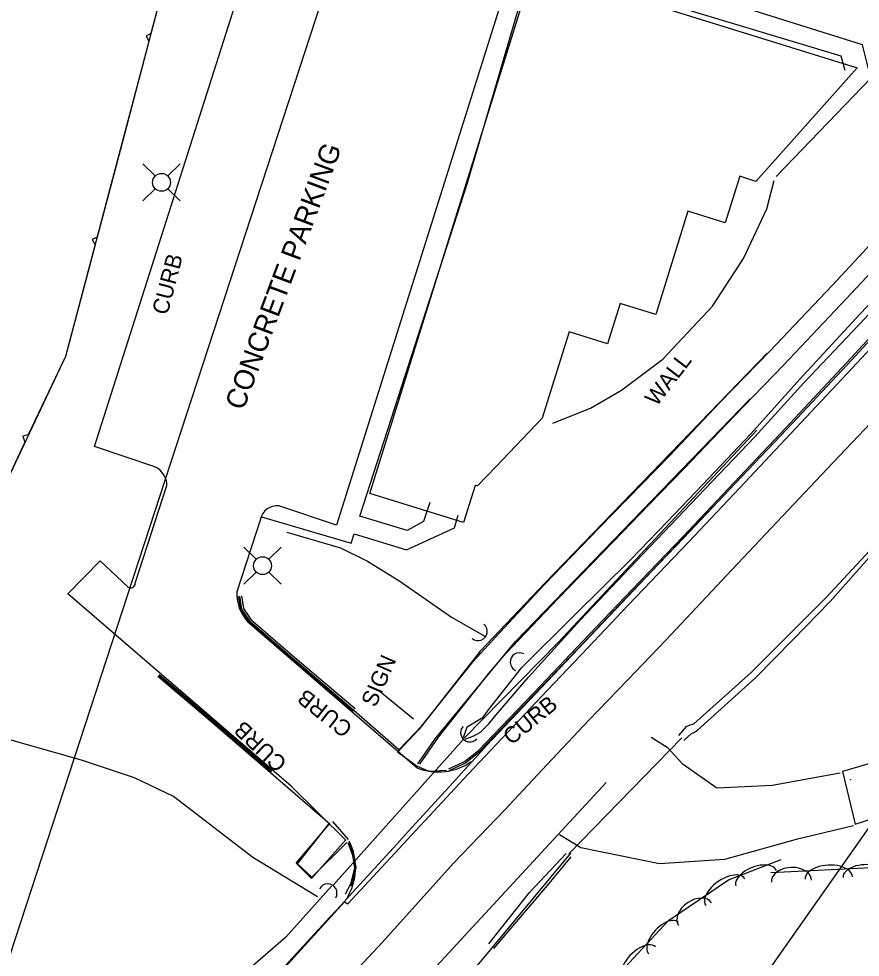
# Model space of a CAD drawing. Extents: x 978516 to 993312, y 1836504 to 1846212.
# Drawn here: x 982203.8 to 982411.6, y 1842943.3 to 1843174.9 of the extents above; entities that cross this region are included whole.
import ezdxf

# ---------------------------------------------------------------- set-up
doc = ezdxf.new("R2010")
doc.units = 0
for name, color, linetype in [('S_BUILDING', 7, 'Continuous'), ('S_CROSS_DRAIN', 7, 'Continuous'), ('S_CURB', 7, 'Continuous'), ('S_CURB_ANNOT', 7, 'Continuous'), ('S_DITCHLINE', 7, 'Continuous'), ('S_DRIVEWAY', 7, 'Continuous'), ('S_EDGE_CONCRETE', 7, 'Continuous'), ('S_EDGE_PAVEMENT', 7, 'Continuous'), ('S_IRON_PIN_ANNOT', 7, 'Continuous'), ('S_MSC_PT_SYM', 7, 'Continuous'), ('S_PARKING', 7, 'Continuous'), ('S_PARKING_ANNOT', 7, 'Continuous'), ('S_PAVEMENT_CROWN', 7, 'Continuous'), ('S_SIDE_DRAIN', 7, 'Continuous'), ('S_SIDEWALK', 7, 'Continuous'), ('S_SIGN', 7, 'Continuous'), ('S_SIGN_ANNOT', 7, 'Continuous'), ('S_STREAM', 7, 'Continuous'), ('S_TREE', 7, 'Continuous'), ('S_UTILITY_POLE', 7, 'Continuous'), ('S_WALL_ANNOT', 7, 'Continuous')]:
    doc.layers.add(name, color=color, linetype=linetype)

msp = doc.modelspace()

# ---------------------------------------------------------------- linework, layer by layer
at = {"layer": 'S_BUILDING'}
msp.add_lwpolyline([(982290.5, 1843057.74), (982330.9, 1843187.63), (982410.76, 1843162.8), (982385.82, 1843134.75), (982381.83, 1843136.09), (982378.24, 1843124.54), (982369.01, 1843127.41), (982361.09, 1843101.95), (982352.31, 1843104.68), (982349.2, 1843094.68), (982339.69, 1843097.63), (982333.07, 1843076.34), (982321.59, 1843064.31), (982317.04, 1843059.59), (982316.52, 1843059.75), (982313.65, 1843050.54)], close=True, dxfattribs=at)
at = {"layer": 'S_CROSS_DRAIN'}
for centre, start, end in [((982317.18, 1843023.71), 231.2419, 51.5711), ((982327.45, 1843016.11), 63.0314, 243.3606), ((982315.2, 1842998.71), 137.6159, 317.9451), ((982280.09, 1842959.05), 330.1073, 150.4365)]:
    msp.add_arc(centre, 2.3, start, end, dxfattribs=at)
at = {"layer": 'S_CURB'}
for points in [[(982310.01, 1842989.75), (982313.88, 1842991.61), (982317.2, 1842994.25), (982332.7, 1843010.35), (982343.01, 1843021.21), (982353.32, 1843032.07), (982367.67, 1843046.99), (982380.41, 1843060.45), (982393.16, 1843073.92), (982409.26, 1843091.11), (982418.22, 1843100.89), (982427.18, 1843110.67), (982434.94, 1843124.55)], [(982310.01, 1842989.75), (982313.88, 1842991.61), (982317.2, 1842994.25), (982332.7, 1843010.35), (982343.01, 1843021.21), (982353.32, 1843032.07), (982367.67, 1843046.99), (982380.41, 1843060.45), (982393.16, 1843073.92), (982409.26, 1843091.11), (982418.22, 1843100.89), (982427.18, 1843110.67), (982434.94, 1843124.55)], [(982310.19, 1842989.39), (982314.09, 1842991.27), (982317.47, 1842993.96), (982332.99, 1843010.07), (982343.3, 1843020.93), (982353.61, 1843031.79), (982367.95, 1843046.71), (982380.7, 1843060.18), (982393.45, 1843073.64), (982409.55, 1843090.84), (982418.53, 1843100.64), (982427.5, 1843110.44), (982435.29, 1843124.36)], [(982310.19, 1842989.39), (982314.09, 1842991.27), (982317.47, 1842993.96), (982332.99, 1843010.07), (982343.3, 1843020.93), (982353.61, 1843031.79), (982367.95, 1843046.71), (982380.7, 1843060.18), (982393.45, 1843073.64), (982409.55, 1843090.84), (982418.53, 1843100.64), (982427.5, 1843110.44), (982435.29, 1843124.36)], [(982258, 1843032.32), (982258.55, 1843029.05), (982260.55, 1843026.07), (982272, 1843016.16), (982286.37, 1843004.04)], [(982258.3, 1843032.37), (982258.83, 1843029.16), (982260.78, 1843026.27), (982272.19, 1843016.39), (982286.57, 1843004.26), (982297.68, 1842994.54)], [(982238.2, 1843012.67), (982250.58, 1843002.14), (982266, 1842988.86), (982280.62, 1842976.23)], [(982238.39, 1843012.9), (982250.78, 1843002.37), (982266.2, 1842989.08)], [(982238.39, 1843012.9), (982250.78, 1843002.37), (982266.2, 1842989.08)], [(982285.07, 1842971.56), (982286.25, 1842968.42), (982286.74, 1842965.35), (982285.69, 1842961.28), (982284.44, 1842958.81)], [(982285.42, 1842971.49), (982286.54, 1842968.5), (982287.04, 1842965.33), (982285.98, 1842961.18), (982285.78, 1842960.79)]]:
    msp.add_lwpolyline(points, dxfattribs=at)
at = {"layer": 'S_DITCHLINE'}
for points in [[(982313.59, 1842997.52), (982314.52, 1843000.14), (982318.5, 1843002.54), (982319.75, 1843004.37), (982328.05, 1843014.77), (982341.11, 1843027.79), (982354.9, 1843041.43), (982363.81, 1843050.68), (982372.72, 1843059.93), (982384.54, 1843072.5), (982396.63, 1843085.98), (982411.57, 1843102.1), (982419.68, 1843110.65), (982424, 1843116.04), (982429.13, 1843125.27), (982430.93, 1843128.27), (982432.31, 1843130.79), (982432.8, 1843131.44), (982434.64, 1843132.19), (982437.24, 1843133.95)], [(982313.59, 1842997.52), (982314.52, 1843000.14), (982318.5, 1843002.54), (982319.75, 1843004.37), (982328.05, 1843014.77), (982341.11, 1843027.79), (982354.9, 1843041.43), (982363.81, 1843050.68), (982372.72, 1843059.93), (982384.54, 1843072.5), (982396.63, 1843085.98), (982411.57, 1843102.1), (982419.68, 1843110.65), (982424, 1843116.04), (982429.13, 1843125.27), (982430.93, 1843128.27), (982432.31, 1843130.79), (982432.8, 1843131.44), (982434.64, 1843132.19), (982437.24, 1843133.95)], [(982314.07, 1842997.1), (982316.2, 1842997.94), (982317.81, 1842998.81), (982319.86, 1843000.89), (982321.69, 1843003.14), (982329.58, 1843012.28), (982342.49, 1843026.52), (982356.26, 1843041), (982373.23, 1843058.77), (982385.5, 1843071.71), (982397.63, 1843085.05), (982412.79, 1843101.02), (982420.69, 1843109.93), (982424.98, 1843115.3), (982430.76, 1843124.87), (982431.76, 1843127.66), (982432.61, 1843128.21)], [(982314.07, 1842997.1), (982316.2, 1842997.94), (982317.81, 1842998.81), (982319.86, 1843000.89), (982321.69, 1843003.14), (982329.58, 1843012.28), (982342.49, 1843026.52), (982356.26, 1843041), (982373.23, 1843058.77), (982385.5, 1843071.71), (982397.63, 1843085.05), (982412.79, 1843101.02), (982420.69, 1843109.93), (982424.98, 1843115.3), (982430.76, 1843124.87), (982431.76, 1843127.66), (982432.61, 1843128.21)], [(982366.78, 1842998.03), (982368.67, 1843000.22), (982369.54, 1843000.64), (982370.5, 1843000.9), (982384.64, 1843013.54), (982393.93, 1843022.83), (982403.23, 1843032.13), (982419.18, 1843049.38)], [(982366.78, 1842998.03), (982368.67, 1843000.22), (982369.54, 1843000.64), (982370.5, 1843000.9), (982384.64, 1843013.54), (982393.93, 1843022.83), (982403.23, 1843032.13), (982419.18, 1843049.38)], [(982367.98, 1842996.74), (982369.91, 1842998.51), (982370.31, 1842998.64), (982371.31, 1842999.2), (982385.67, 1843012.22), (982394.91, 1843021.65), (982404.14, 1843031.08), (982420.18, 1843049.22)], [(982319.89, 1842946.58), (982329.95, 1842959.26), (982338.95, 1842968.86)], [(982340.1, 1842968.01), (982334.26, 1842960.95), (982321, 1842945.38)]]:
    msp.add_lwpolyline(points, dxfattribs=at)
at = {"layer": 'S_DRIVEWAY'}
for points in [[(982258.79, 1843032.45), (982259.31, 1843029.35), (982261.16, 1843026.61), (982272.52, 1843016.77), (982286.89, 1843004.64)], [(982238.52, 1843013.05), (982250.91, 1843002.52), (982266.33, 1842989.24)], [(982238.52, 1843013.05), (982250.91, 1843002.52), (982266.33, 1842989.24)], [(982359.97, 1842997.61), (982363.91, 1842995.15), (982367.56, 1842991.1), (982376.15, 1842985.11), (982389.79, 1842985.76), (982406.62, 1842988.77)], [(982359.97, 1842997.61), (982363.91, 1842995.15), (982367.56, 1842991.1), (982376.15, 1842985.11), (982389.79, 1842985.76), (982406.62, 1842988.77)], [(982297.36, 1842993.94), (982302.17, 1842990.4), (982305.02, 1842989.2), (982309.43, 1842989.41)], [(982281.32, 1842976.8), (982285.15, 1842972.33)], [(982409.93, 1842975.74), (982395.76, 1842972.31), (982378.01, 1842967.38), (982361.97, 1842966.36), (982342.56, 1842970.27), (982337.35, 1842973.46)], [(982409.93, 1842975.74), (982395.76, 1842972.31), (982378.01, 1842967.38), (982361.97, 1842966.36), (982342.56, 1842970.27), (982337.35, 1842973.46)]]:
    msp.add_lwpolyline(points, dxfattribs=at)
at = {"layer": 'S_EDGE_CONCRETE'}
for points in [[(982410.28, 1842976.09), (982425.13, 1842980.92), (982422.37, 1842993.58), (982407.2, 1842989.13)], [(982407.2, 1842989.13), (982410.28, 1842976.09)]]:
    msp.add_lwpolyline(points, dxfattribs=at)
at = {"layer": 'S_EDGE_PAVEMENT'}
for points in [[(982262.81, 1842933.38), (982273.52, 1842945.14), (982284.22, 1842956.91), (982285.09, 1842956.45), (982301.82, 1842974.54), (982314.78, 1842988.42), (982324.57, 1842998.8), (982334.36, 1843009.18), (982344.31, 1843019.68), (982354.26, 1843030.18), (982369.14, 1843045.7), (982381.73, 1843059.08), (982394.31, 1843072.45), (982410.8, 1843089.97), (982425.98, 1843106.39), (982439.97, 1843122.26), (982437.62, 1843124.47), (982439.48, 1843126.59), (982448.32, 1843135.88), (982456.89, 1843144.96), (982470.98, 1843160.83), (982473.17, 1843164.88), (982487.85, 1843181.85)], [(982262.81, 1842933.38), (982273.52, 1842945.14), (982284.22, 1842956.91), (982285.09, 1842956.45), (982301.82, 1842974.54), (982314.78, 1842988.42), (982324.57, 1842998.8), (982334.36, 1843009.18), (982344.31, 1843019.68), (982354.26, 1843030.18), (982369.14, 1843045.7), (982381.73, 1843059.08), (982394.31, 1843072.45), (982410.8, 1843089.97), (982425.98, 1843106.39), (982439.97, 1843122.26), (982437.62, 1843124.47), (982439.48, 1843126.59), (982448.32, 1843135.88), (982456.89, 1843144.96), (982470.98, 1843160.83), (982473.17, 1843164.88), (982487.85, 1843181.85)], [(982319.32, 1842995.54), (982375.31, 1843054.59)], [(982348.83, 1842986.38), (982259.18, 1842889.28), (982226.37, 1842852.75)]]:
    msp.add_lwpolyline(points, dxfattribs=at)
msp.add_ellipse((982031.71, 1843314.23), major_axis=(1334.75, 1486.11), ratio=0.213781, start_param=4.624147, end_param=4.689901, dxfattribs=at)
at = {"layer": 'S_IRON_PIN_ANNOT'}
msp.add_lwpolyline([(982335.67, 1843075.11), (982344.96, 1843078.82), (982352.58, 1843083.22), (982362.84, 1843090.89), (982375.05, 1843103.96), (982382.71, 1843115.72), (982388.47, 1843128.01), (982390.29, 1843135)], dxfattribs=at)
at = {"layer": 'S_MSC_PT_SYM'}
msp.add_lwpolyline([(982409.17, 1842987.12), (982409.17, 1842987.17), (982409.17, 1842987.12), (982409.12, 1842987.12), (982409.17, 1842987.12), (982409.17, 1842987.07), (982409.17, 1842987.12), (982409.22, 1842987.12)], dxfattribs=at)
at = {"layer": 'S_PARKING'}
for points in [[(982237.45, 1843064.3), (982222.53, 1843069.32), (982263.23, 1843197.33), (982279.77, 1843192.12)], [(982237.45, 1843064.3), (982222.53, 1843069.32), (982263.23, 1843197.33), (982279.77, 1843192.12)], [(982237.45, 1843064.3), (982222.53, 1843069.32), (982263.23, 1843197.33), (982279.77, 1843192.12)], [(982305.84, 1843183.12), (982322.39, 1843177.48), (982282.24, 1843049.96), (982268.03, 1843054.67)], [(982305.84, 1843183.12), (982322.39, 1843177.48), (982282.24, 1843049.96), (982268.03, 1843054.67)], [(982305.84, 1843183.12), (982322.39, 1843177.48), (982282.24, 1843049.96), (982268.03, 1843054.67)], [(982232.56, 1843035.63), (982240.42, 1843059.74)], [(982232.56, 1843035.63), (982240.42, 1843059.74)], [(982232.56, 1843035.63), (982240.42, 1843059.74)], [(982263.47, 1843051.39), (982257.63, 1843033.46)], [(982263.47, 1843051.39), (982257.63, 1843033.46)], [(982263.47, 1843051.39), (982257.63, 1843033.46)], [(982284.68, 1842972.07), (982271.1, 1842985.51), (982215.92, 1843032.98), (982223.89, 1843041.15), (982230.74, 1843034.68)], [(982284.68, 1842972.07), (982271.1, 1842985.51), (982215.92, 1843032.98), (982223.89, 1843041.15), (982230.74, 1843034.68)], [(982284.68, 1842972.07), (982271.1, 1842985.51), (982215.92, 1843032.98), (982223.89, 1843041.15), (982230.74, 1843034.68)], [(982260.26, 1843026.14), (982302.18, 1842989.98)], [(982260.26, 1843026.14), (982302.18, 1842989.98)], [(982260.26, 1843026.14), (982302.18, 1842989.98)]]:
    msp.add_lwpolyline(points, dxfattribs=at)
for centre, major_axis, ratio, start_param, end_param in [((982237.16, 1843060.88), (-2.2, 3.3), 0.729044, 3.943969, 5.454657), ((982237.16, 1843060.88), (-2.2, 3.3), 0.729044, 3.943969, 5.454657), ((982237.16, 1843060.88), (-2.2, 3.3), 0.729044, 3.943969, 5.454657), ((982267.51, 1843050.53), (0.48, 4.14), 0.989001, 6.273379, 7.760035), ((982267.51, 1843050.53), (0.48, 4.14), 0.989001, 6.273379, 7.760035), ((982267.51, 1843050.53), (0.48, 4.14), 0.989001, 6.273379, 7.760035), ((982231.41, 1843035.56), (1.06, -0.48), 0.95124, 4.498397, 6.784956), ((982231.41, 1843035.56), (1.06, -0.48), 0.95124, 4.498397, 6.784956), ((982231.41, 1843035.56), (1.06, -0.48), 0.95124, 4.498397, 6.784956), ((982268.46, 1843033.26), (0, -10.9), 0.993118, 4.694677, 5.424665), ((982268.46, 1843033.26), (0, -10.9), 0.993118, 4.694677, 5.424665), ((982268.46, 1843033.26), (0, -10.9), 0.993118, 4.694677, 5.424665), ((982307.52, 1843000.62), (12.96, 0.65), 0.894333, 4.243565, 5.329373), ((982307.52, 1843000.62), (12.96, 0.65), 0.894333, 4.243565, 5.329373), ((982307.52, 1843000.62), (12.96, 0.65), 0.894333, 4.243565, 5.329373), ((982272.39, 1842965.26), (11.61, 8.88), 0.992741, 5.081123, 6.100349)]:
    msp.add_ellipse(centre, major_axis=major_axis, ratio=ratio, start_param=start_param, end_param=end_param, dxfattribs=at)
at = {"layer": 'S_PAVEMENT_CROWN'}
msp.add_lwpolyline([(982282.98, 1842935.62), (982293.66, 1842947), (982302.39, 1842956.74), (982311.12, 1842966.49), (982323.85, 1842979.66), (982334.21, 1842990.74), (982344.56, 1843001.82), (982354.08, 1843011.66), (982363.59, 1843021.51), (982378.65, 1843037.56), (982390.97, 1843050.64), (982403.29, 1843063.73), (982420.37, 1843081.7), (982434.99, 1843097.55), (982448.57, 1843111.64), (982459.98, 1843124.19), (982470.63, 1843135.54), (982484.52, 1843150.65), (982494.5, 1843162.1), (982504.48, 1843173.55), (982517.52, 1843188.84)], dxfattribs=at)
at = {"layer": 'S_SIDE_DRAIN'}
for p, q in [((982281.53, 1842961.15), (982313.68, 1842997.2)), ((982339.6, 1842968.75), (982367.51, 1842997.41))]:
    msp.add_line(p, q, dxfattribs=at)
at = {"layer": 'S_SIDEWALK'}
for points in [[(982390.8, 1843135.97), (982414.13, 1843160.29), (982412.14, 1843168.51), (982333.42, 1843193.22), (982326.15, 1843189.45), (982322.34, 1843177.58)], [(982305.3, 1843055.48), (982303.76, 1843050.81), (982299.68, 1843048.58), (982288.06, 1843052.16), (982314.57, 1843134.46), (982329.35, 1843184.77), (982333.71, 1843187.81), (982406.79, 1843165.77), (982407.78, 1843162.25)], [(982297.79, 1842994.59), (982303.36, 1843000.42), (982316.12, 1843016.33), (982320.57, 1843021.22), (982333.52, 1843035.16), (982347.16, 1843049.35), (982364.57, 1843067.13), (982376.95, 1843080.27), (982389.24, 1843092.86), (982404.62, 1843109.11), (982412.24, 1843117.28), (982417.07, 1843122.54), (982433.13, 1843139.54), (982445.17, 1843151.93), (982457.08, 1843164.66), (982464.33, 1843172.15), (982469.15, 1843178.53)], [(982297.79, 1842994.59), (982303.36, 1843000.42), (982316.12, 1843016.33), (982320.57, 1843021.22), (982333.52, 1843035.16), (982347.16, 1843049.35), (982364.57, 1843067.13), (982376.95, 1843080.27), (982389.24, 1843092.86), (982404.62, 1843109.11), (982412.24, 1843117.28), (982417.07, 1843122.54), (982433.13, 1843139.54), (982445.17, 1843151.93), (982457.08, 1843164.66), (982464.33, 1843172.15), (982469.15, 1843178.53)], [(982302.84, 1842990.91), (982307.45, 1842997.59), (982319.82, 1843013.22), (982324.05, 1843018.23), (982337.01, 1843031.78), (982350.66, 1843045.92), (982359.35, 1843054.9), (982368.05, 1843063.89), (982380.33, 1843076.77), (982392.72, 1843089.54), (982408.07, 1843105.75), (982415.77, 1843113.91), (982420.39, 1843118.84), (982436.22, 1843135.72), (982448.71, 1843149.05), (982460.53, 1843161.31), (982467.87, 1843168.8), (982471.61, 1843172.36)], [(982302.84, 1842990.91), (982307.45, 1842997.59), (982319.82, 1843013.22), (982324.05, 1843018.23), (982337.01, 1843031.78), (982350.66, 1843045.92), (982359.35, 1843054.9), (982368.05, 1843063.89), (982380.33, 1843076.77), (982392.72, 1843089.54), (982408.07, 1843105.75), (982415.77, 1843113.91), (982420.39, 1843118.84), (982436.22, 1843135.72), (982448.71, 1843149.05), (982460.53, 1843161.31), (982467.87, 1843168.8), (982471.61, 1843172.36)], [(982388.58, 1843092.34), (982333.79, 1843035.68), (982317.71, 1843018.84), (982302.66, 1842999.6), (982297.57, 1842994.15)], [(982302.31, 1842990.99), (982306.59, 1842997.2), (982326.49, 1843021.19), (982384.36, 1843081.09)], [(982263.79, 1843051.98), (982285.92, 1843045.48), (982286.62, 1843047.8), (982299.56, 1843043.83), (982311.43, 1843049.27), (982312.29, 1843052.42)], [(982284.55, 1842972.27), (982276.07, 1842962.74), (982272.28, 1842966.46), (982280.59, 1842976.28)], [(982284.81, 1842971.57), (982276.14, 1842963.03), (982272.66, 1842966.28), (982280.52, 1842976.34)]]:
    msp.add_lwpolyline(points, dxfattribs=at)
at = {"layer": 'S_SIGN'}
msp.add_lwpolyline([(982301.29, 1843002.03), (982292.58, 1843009.2)], dxfattribs=at)
at = {"layer": 'S_STREAM'}
for points in [[(982313.77, 1842997.32), (982337, 1843020.93), (982386.02, 1843073.41)], [(982270.02, 1843048.23), (982283.29, 1843044.29), (982289.91, 1843041.02), (982297.93, 1843036.06), (982310.63, 1843027.24), (982318.91, 1843022.54)], [(982277.55, 1842958.19), (982261.58, 1842967.88), (982242.05, 1842982.94), (982232.41, 1842987.57), (982219.33, 1842991.88), (982195.45, 1842998.69)], [(982222.65, 1842836.43), (982238.5, 1842853.87), (982254.52, 1842870.47), (982275.18, 1842892.66), (982311.81, 1842934.86), (982340.08, 1842968.96)], [(982281, 1842960.79), (982269.77, 1842948.2), (982243.89, 1842925.72)]]:
    msp.add_lwpolyline(points, dxfattribs=at)
at = {"layer": 'S_TREE'}
for p, q in [((982236.47, 1843171.29), (982235.26, 1843170.67)), ((982235.26, 1843170.67), (982235.97, 1843169.39)), ((982223.2, 1843121.04), (982221.99, 1843120.42)), ((982221.99, 1843120.42), (982222.7, 1843119.14)), ((982206.19, 1843072.18), (982204.88, 1843071.85)), ((982204.88, 1843071.85), (982205.34, 1843070.41))]:
    msp.add_line(p, q, dxfattribs=at)
for points in [[(982300.44, 1843395.05), (982280.62, 1843319.54), (982253.69, 1843236.78), (982235.63, 1843168.07), (982215.41, 1843091.54), (982197.48, 1843053.9), (982192.61, 1843036.31), (982188.09, 1843001.09), (982184.58, 1842981.39), (982173.44, 1842932.28)], [(982242.83, 1843195.46), (982236.47, 1843171.29)], [(982235.97, 1843169.39), (982235.63, 1843168.07), (982229.59, 1843145.21)], [(982229.59, 1843145.21), (982223.2, 1843121.04)], [(982222.7, 1843119.14), (982216.31, 1843094.97)], [(982216.31, 1843094.97), (982215.41, 1843091.54), (982206.19, 1843072.18)], [(982205.34, 1843070.41), (982197.48, 1843053.9), (982195.7, 1843047.45)], [(982413.71, 1842875.08), (982393.87, 1842847), (982381.93, 1842835.83), (982365.87, 1842824.46), (982346.34, 1842817.63), (982337.47, 1842825.51), (982340.22, 1842837.08), (982336.25, 1842851.99), (982329.44, 1842866.2), (982318.23, 1842876.92), (982324.22, 1842893.86), (982336.41, 1842919.25), (982348.07, 1842934.95), (982364.26, 1842952.34), (982379.06, 1842962.4), (982392.01, 1842967.36)], [(982389.5, 1842964.16), (982415.93, 1842965.53), (982435.9, 1842961.46), (982447.59, 1842954.71), (982459.83, 1842947.27), (982461.6, 1842946.29)]]:
    msp.add_lwpolyline(points, dxfattribs=at)
for centre, major_axis, ratio, start_param, end_param in [((982385.86, 1842962.78), (-4.98, -1.93), 0.528966, 3.133781, 6.275374), ((982403.79, 1842962.8), (-5.86, -0.31), 0.545027, 3.138751, 6.280344), ((982412.65, 1842963.25), (-5.34, -0.28), 0.535733, 3.138839, 6.280432), ((982378.26, 1842959.36), (-4.83, -3.32), 0.536831, 3.132851, 6.274444), ((982394.56, 1842962.06), (-4.95, -0.27), 0.679012, 3.136975, 6.278568), ((982370.75, 1842953.94), (-4.07, -2.82), 0.668769, 3.127568, 6.26916), ((982363.04, 1842947.99), (-3.63, -3.92), 0.52737, 3.135953, 6.277546), ((982357, 1842941.51), (-3.98, -4.3), 0.536519, 3.135777, 6.27737)]:
    msp.add_ellipse(centre, major_axis=major_axis, ratio=ratio, start_param=start_param, end_param=end_param, dxfattribs=at)
at = {"layer": 'S_UTILITY_POLE'}
for p, q in [((982237.48, 1843136.12), (982234.5, 1843139.11)), ((982240.66, 1843136.12), (982243.65, 1843139.11)), ((982237.48, 1843132.94), (982234.5, 1843129.96)), ((982240.66, 1843132.94), (982243.65, 1843129.96)), ((982262.41, 1843041.5), (982259.43, 1843044.49)), ((982265.59, 1843041.5), (982268.58, 1843044.49)), ((982262.41, 1843038.33), (982259.43, 1843035.34)), ((982265.59, 1843038.33), (982268.58, 1843035.34))]:
    msp.add_line(p, q, dxfattribs=at)
for points in [[(982373.53, 1843470.23), (982185.69, 1842895.12)], [(982155.2, 1842500.71), (982199.63, 1842680.02), (982312.05, 1842830.61), (982495.42, 1843091.36)]]:
    msp.add_lwpolyline(points, dxfattribs=at)
for centre in [(982239.08, 1843134.54), (982264.01, 1843039.92)]:
    msp.add_circle(centre, 2.21, dxfattribs=at)

# ---------------------------------------------------------------- texts
at = {"layer": 'S_CURB_ANNOT'}
for rotation, p in [(75.4243, (982240.54, 1843101.61)), (141.733, (982286.54, 1843000.32)), (39.3082, (982325.45, 1842995.47)), (136.6692, (982270.32, 1842991.5))]:
    msp.add_text('CURB', height=4, rotation=rotation, dxfattribs=at).set_placement(p)
at = {"layer": 'S_PARKING_ANNOT'}
msp.add_text('CONCRETE PARKING', height=5.0005, rotation=69.5021, dxfattribs=at).set_placement((982259.28, 1843078.02))
at = {"layer": 'S_SIGN_ANNOT'}
msp.add_text('SIGN', height=4, rotation=66.4174, dxfattribs=at).set_placement((982291.89, 1843004.74))
at = {"layer": 'S_WALL_ANNOT'}
msp.add_text('WALL', height=4, rotation=52.4632, dxfattribs=at).set_placement((982361.28, 1843079.03))

doc.saveas('drawing.dxf')
